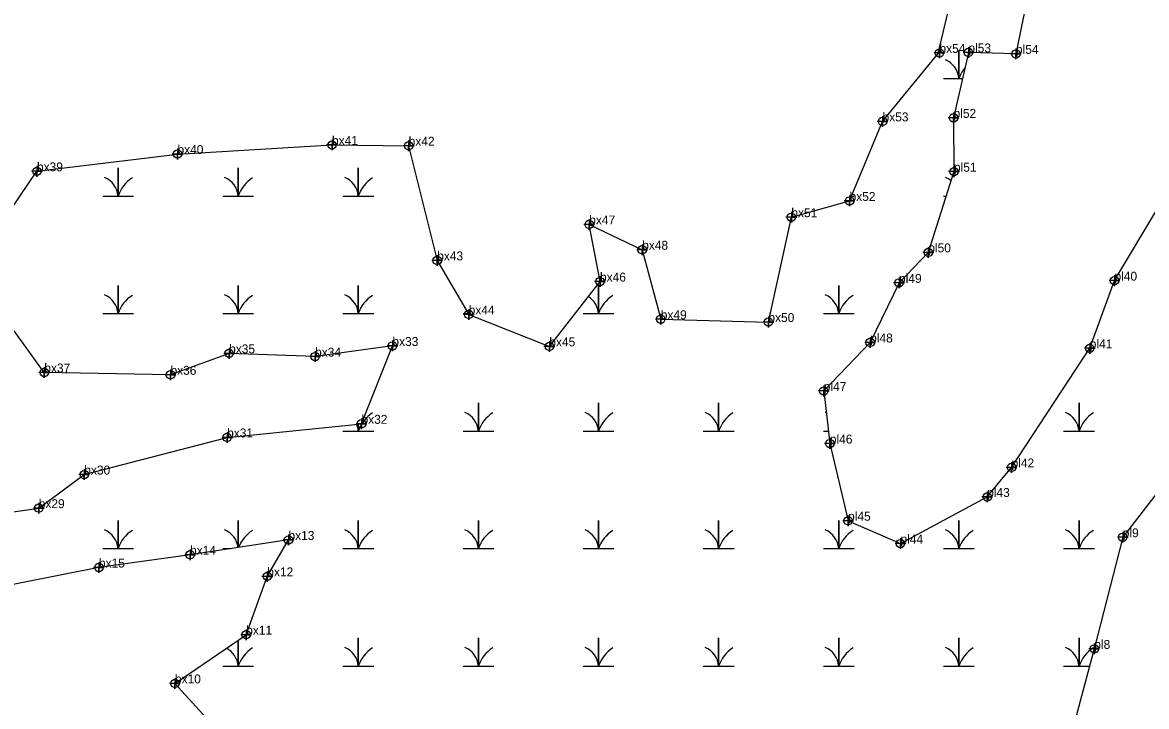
# Model space of a CAD drawing. Extents: x 2071991 to 2268989, y 436479 to 469629.
# Drawn here: x 2233643 to 2234271, y 438038 to 438420 of the extents above; entities that cross this region are included whole.
import ezdxf

# ---------------------------------------------------------------- set-up
doc = ezdxf.new("R2010")
doc.units = 0
for name, color, linetype in [('Exist Environmental Wetland Boundary', 7, 'Continuous'), ('Exist Environmental Wetland Boundary Cogo Comment', 7, 'Continuous'), ('Exist Environmental Wetland Boundary Cogo Point CELL', 7, 'Continuous'), ('Exist Hydro Swamp or Marsh', 7, 'Continuous')]:
    doc.layers.add(name, color=color, linetype=linetype)

msp = doc.modelspace()

# ---------------------------------------------------------------- linework, layer by layer
at = {"layer": 'Exist Environmental Wetland Boundary'}
for points in [[(2234206.5, 438606.87), (2234215.25, 438571.96), (2234220.38, 438527.18), (2234204.32, 438480.7), (2234205.77, 438439.37), (2234198.43, 438402.89), (2234171.84, 438403.69), (2234163.55, 438367.07), (2234163.75, 438336.95), (2234149.39, 438291.75), (2234133.01, 438274.68), (2234116.86, 438241.33), (2234090.91, 438214.16), (2234094.32, 438184.72), (2234104.51, 438141.53), (2234133.82, 438128.75), (2234182.34, 438154.84), (2234196, 438171.36), (2234239.71, 438238.05), (2234253.57, 438275.93), (2234280.54, 438321.15)], [(2233617.82, 438143.72), (2233651.73, 438148.58), (2233677.19, 438167.39), (2233757.1, 438188.17), (2233832.28, 438195.79), (2233849.59, 438239.38), (2233806.32, 438233.44), (2233758.21, 438235.23), (2233725.42, 438223.22), (2233654.83, 438224.52), (2233613.07, 438282.03), (2233650.73, 438337.13), (2233729.33, 438346.82), (2233815.78, 438351.89), (2233858.66, 438351.45), (2233874.62, 438287.27), (2233892.26, 438257), (2233937.37, 438239.13), (2233965.72, 438275.42), (2233959.69, 438307.4), (2233989.31, 438293.23), (2233999.72, 438254.31), (2234059.94, 438252.78), (2234072.76, 438311.45), (2234105.34, 438320.55), (2234123.8, 438365.08), (2234155, 438403.07), (2234167.55, 438456.6)], [(2234279.17, 438159.32), (2234258.17, 438132.28), (2234242.26, 438069.78), (2234230.04, 438024.51), (2234217.72, 437985.47), (2234249.98, 437934.73), (2234302.96, 437891.47)], [(2233878.1, 437800.94), (2233869.26, 437811.67), (2233815.49, 437844.98), (2233781.11, 437879.68), (2233780.48, 437926.57), (2233771.05, 437964.06), (2233759.41, 438015.96), (2233727.92, 438050.47), (2233767.76, 438077.73), (2233779.58, 438110.39), (2233791.43, 438130.77), (2233736.36, 438122.5), (2233685.39, 438115.35), (2233620.22, 438102.5)]]:
    msp.add_lwpolyline(points, dxfattribs=at)
at = {"layer": 'Exist Environmental Wetland Boundary Cogo Point CELL'}
for points in [[(2234155.64, 438406.39), (2234155.64, 438400.39), (2234155.64, 438403.39), (2234158.64, 438403.39), (2234152.64, 438403.39)], [(2234171.84, 438406.69), (2234171.84, 438400.69), (2234171.84, 438403.69), (2234174.84, 438403.69), (2234168.84, 438403.69)], [(2234198.43, 438405.89), (2234198.43, 438399.89), (2234198.43, 438402.89), (2234201.43, 438402.89), (2234195.43, 438402.89)], [(2234123.8, 438368.08), (2234123.8, 438362.08), (2234123.8, 438365.08), (2234126.8, 438365.08), (2234120.8, 438365.08)], [(2234163.55, 438370.07), (2234163.55, 438364.07), (2234163.55, 438367.07), (2234166.55, 438367.07), (2234160.55, 438367.07)], [(2233815.78, 438354.89), (2233815.78, 438348.89), (2233815.78, 438351.89), (2233818.78, 438351.89), (2233812.78, 438351.89)], [(2233858.66, 438354.45), (2233858.66, 438348.45), (2233858.66, 438351.45), (2233861.66, 438351.45), (2233855.66, 438351.45)], [(2233729.33, 438349.82), (2233729.33, 438343.82), (2233729.33, 438346.82), (2233732.33, 438346.82), (2233726.33, 438346.82)], [(2233650.73, 438340.13), (2233650.73, 438334.13), (2233650.73, 438337.13), (2233653.73, 438337.13), (2233647.73, 438337.13)], [(2234163.75, 438339.95), (2234163.75, 438333.95), (2234163.75, 438336.95), (2234166.75, 438336.95), (2234160.75, 438336.95)], [(2234105.34, 438323.55), (2234105.34, 438317.55), (2234105.34, 438320.55), (2234108.34, 438320.55), (2234102.34, 438320.55)], [(2234072.76, 438314.45), (2234072.76, 438308.45), (2234072.76, 438311.45), (2234075.76, 438311.45), (2234069.76, 438311.45)], [(2233959.69, 438310.4), (2233959.69, 438304.4), (2233959.69, 438307.4), (2233962.69, 438307.4), (2233956.69, 438307.4)], [(2233989.31, 438296.23), (2233989.31, 438290.23), (2233989.31, 438293.23), (2233992.31, 438293.23), (2233986.31, 438293.23)], [(2233874.62, 438290.27), (2233874.62, 438284.27), (2233874.62, 438287.27), (2233877.62, 438287.27), (2233871.62, 438287.27)], [(2234149.39, 438294.75), (2234149.39, 438288.75), (2234149.39, 438291.75), (2234152.39, 438291.75), (2234146.39, 438291.75)], [(2233965.72, 438278.42), (2233965.72, 438272.42), (2233965.72, 438275.42), (2233968.72, 438275.42), (2233962.72, 438275.42)], [(2234133.01, 438277.68), (2234133.01, 438271.68), (2234133.01, 438274.68), (2234136.01, 438274.68), (2234130.01, 438274.68)], [(2234253.57, 438278.93), (2234253.57, 438272.93), (2234253.57, 438275.93), (2234256.57, 438275.93), (2234250.57, 438275.93)], [(2233892.26, 438260), (2233892.26, 438254), (2233892.26, 438257), (2233895.26, 438257), (2233889.26, 438257)], [(2233999.72, 438257.31), (2233999.72, 438251.31), (2233999.72, 438254.31), (2234002.72, 438254.31), (2233996.72, 438254.31)], [(2234059.94, 438255.78), (2234059.94, 438249.78), (2234059.94, 438252.78), (2234062.94, 438252.78), (2234056.94, 438252.78)], [(2233849.59, 438242.38), (2233849.59, 438236.38), (2233849.59, 438239.38), (2233852.59, 438239.38), (2233846.59, 438239.38)], [(2233937.37, 438242.13), (2233937.37, 438236.13), (2233937.37, 438239.13), (2233940.37, 438239.13), (2233934.37, 438239.13)], [(2234116.86, 438244.33), (2234116.86, 438238.33), (2234116.86, 438241.33), (2234119.86, 438241.33), (2234113.86, 438241.33)], [(2234239.71, 438241.05), (2234239.71, 438235.05), (2234239.71, 438238.05), (2234242.71, 438238.05), (2234236.71, 438238.05)], [(2233758.21, 438238.23), (2233758.21, 438232.23), (2233758.21, 438235.23), (2233761.21, 438235.23), (2233755.21, 438235.23)], [(2233806.32, 438236.44), (2233806.32, 438230.44), (2233806.32, 438233.44), (2233809.32, 438233.44), (2233803.32, 438233.44)], [(2233654.83, 438227.52), (2233654.83, 438221.52), (2233654.83, 438224.52), (2233657.83, 438224.52), (2233651.83, 438224.52)], [(2233725.42, 438226.22), (2233725.42, 438220.22), (2233725.42, 438223.22), (2233728.42, 438223.22), (2233722.42, 438223.22)], [(2234090.91, 438217.16), (2234090.91, 438211.16), (2234090.91, 438214.16), (2234093.91, 438214.16), (2234087.91, 438214.16)], [(2233832.28, 438198.79), (2233832.28, 438192.79), (2233832.28, 438195.79), (2233835.28, 438195.79), (2233829.28, 438195.79)], [(2233757.1, 438191.17), (2233757.1, 438185.17), (2233757.1, 438188.17), (2233760.1, 438188.17), (2233754.1, 438188.17)], [(2234094.32, 438187.72), (2234094.32, 438181.72), (2234094.32, 438184.72), (2234097.32, 438184.72), (2234091.32, 438184.72)], [(2233677.19, 438170.39), (2233677.19, 438164.39), (2233677.19, 438167.39), (2233680.19, 438167.39), (2233674.19, 438167.39)], [(2234196, 438174.36), (2234196, 438168.36), (2234196, 438171.36), (2234199, 438171.36), (2234193, 438171.36)], [(2234182.34, 438157.84), (2234182.34, 438151.84), (2234182.34, 438154.84), (2234185.34, 438154.84), (2234179.34, 438154.84)], [(2233651.73, 438151.58), (2233651.73, 438145.58), (2233651.73, 438148.58), (2233654.73, 438148.58), (2233648.73, 438148.58)], [(2234104.51, 438144.53), (2234104.51, 438138.53), (2234104.51, 438141.53), (2234107.51, 438141.53), (2234101.51, 438141.53)], [(2233791.43, 438133.77), (2233791.43, 438127.77), (2233791.43, 438130.77), (2233794.43, 438130.77), (2233788.43, 438130.77)], [(2234258.17, 438135.28), (2234258.17, 438129.28), (2234258.17, 438132.28), (2234261.17, 438132.28), (2234255.17, 438132.28)], [(2234133.82, 438131.75), (2234133.82, 438125.75), (2234133.82, 438128.75), (2234136.82, 438128.75), (2234130.82, 438128.75)], [(2233736.36, 438125.5), (2233736.36, 438119.5), (2233736.36, 438122.5), (2233739.36, 438122.5), (2233733.36, 438122.5)], [(2233685.39, 438118.35), (2233685.39, 438112.35), (2233685.39, 438115.35), (2233688.39, 438115.35), (2233682.39, 438115.35)], [(2233779.58, 438113.39), (2233779.58, 438107.39), (2233779.58, 438110.39), (2233782.58, 438110.39), (2233776.58, 438110.39)], [(2233767.76, 438080.73), (2233767.76, 438074.73), (2233767.76, 438077.73), (2233770.76, 438077.73), (2233764.76, 438077.73)], [(2234242.26, 438072.78), (2234242.26, 438066.78), (2234242.26, 438069.78), (2234245.26, 438069.78), (2234239.26, 438069.78)], [(2233727.92, 438053.47), (2233727.92, 438047.47), (2233727.92, 438050.47), (2233730.92, 438050.47), (2233724.92, 438050.47)]]:
    msp.add_lwpolyline(points, dxfattribs=at)
for centre in [(2234155.64, 438403.39), (2234171.84, 438403.69), (2234198.43, 438402.89), (2234123.8, 438365.08), (2234163.55, 438367.07), (2233815.78, 438351.89), (2233858.66, 438351.45), (2233729.33, 438346.82), (2233650.73, 438337.13), (2234163.75, 438336.95), (2234105.34, 438320.55), (2233959.69, 438307.4), (2234072.76, 438311.45), (2233989.31, 438293.23), (2233874.62, 438287.27), (2234149.39, 438291.75), (2233965.72, 438275.42), (2234133.01, 438274.68), (2234253.57, 438275.93), (2233892.26, 438257), (2233999.72, 438254.31), (2234059.94, 438252.78), (2233849.59, 438239.38), (2233937.37, 438239.13), (2234116.86, 438241.33), (2234239.71, 438238.05), (2233758.21, 438235.23), (2233806.32, 438233.44), (2233654.83, 438224.52), (2233725.42, 438223.22), (2234090.91, 438214.16), (2233832.28, 438195.79), (2233757.1, 438188.17), (2234094.32, 438184.72), (2233677.19, 438167.39), (2234196, 438171.36), (2234182.34, 438154.84), (2233651.73, 438148.58), (2234104.51, 438141.53), (2233791.43, 438130.77), (2234258.17, 438132.28), (2234133.82, 438128.75), (2233736.36, 438122.5), (2233685.39, 438115.35), (2233779.58, 438110.39), (2233767.76, 438077.73), (2234242.26, 438069.78), (2233727.92, 438050.47)]:
    msp.add_circle(centre, 2.34, dxfattribs=at)
at = {"layer": 'Exist Hydro Swamp or Marsh'}
for p, q in [((2234106.46, 438323.25), (2234107.9, 438323.25)), ((2234157.9, 438323.25), (2234159.4, 438323.25)), ((2233889.09, 438257.47), (2233891.98, 438257.47)), ((2234090.7, 438191.69), (2234093.51, 438191.69)), ((2233754.68, 438125.91), (2233759.08, 438125.91))]:
    msp.add_line(p, q, dxfattribs=at)
for points in [[(2234157.9, 438389.04), (2234166.5, 438389.04), (2234166.5, 438404.82), (2234166.5, 438389.04), (2234168.53, 438389.04)], [(2233687.48, 438323.25), (2233696.08, 438323.25), (2233696.08, 438339.04), (2233696.08, 438323.25), (2233704.68, 438323.25)], [(2233754.68, 438323.25), (2233763.28, 438323.25), (2233763.28, 438339.04), (2233763.28, 438323.25), (2233771.89, 438323.25)], [(2233821.89, 438323.25), (2233830.49, 438323.25), (2233830.49, 438339.04), (2233830.49, 438323.25), (2233839.09, 438323.25)], [(2233687.48, 438257.47), (2233696.08, 438257.47), (2233696.08, 438273.25), (2233696.08, 438257.47), (2233704.68, 438257.47)], [(2233754.68, 438257.47), (2233763.28, 438257.47), (2233763.28, 438273.25), (2233763.28, 438257.47), (2233771.89, 438257.47)], [(2233821.89, 438257.47), (2233830.49, 438257.47), (2233830.49, 438273.25), (2233830.49, 438257.47), (2233839.09, 438257.47)], [(2233956.29, 438257.47), (2233964.89, 438257.47), (2233964.89, 438273.25), (2233964.89, 438257.47), (2233973.5, 438257.47)], [(2234090.7, 438257.47), (2234099.3, 438257.47), (2234099.3, 438273.25), (2234099.3, 438257.47), (2234107.9, 438257.47)], [(2233889.09, 438191.69), (2233897.69, 438191.69), (2233897.69, 438207.47), (2233897.69, 438191.69), (2233906.29, 438191.69)], [(2233956.29, 438191.69), (2233964.89, 438191.69), (2233964.89, 438207.47), (2233964.89, 438191.69), (2233973.5, 438191.69)], [(2234023.5, 438191.69), (2234032.1, 438191.69), (2234032.1, 438207.47), (2234032.1, 438191.69), (2234040.7, 438191.69)], [(2234225.11, 438191.69), (2234233.71, 438191.69), (2234233.71, 438207.47), (2234233.71, 438191.69), (2234242.31, 438191.69)], [(2233821.89, 438191.69), (2233830.49, 438191.69), (2233830.49, 438195.61)], [(2233830.49, 438195.61), (2233830.49, 438191.69), (2233839.09, 438191.69)], [(2233687.48, 438125.91), (2233696.08, 438125.91), (2233696.08, 438141.69), (2233696.08, 438125.91), (2233704.68, 438125.91)], [(2233763.28, 438126.54), (2233763.28, 438141.69), (2233763.28, 438126.54)], [(2233821.89, 438125.91), (2233830.49, 438125.91), (2233830.49, 438141.69), (2233830.49, 438125.91), (2233839.09, 438125.91)], [(2233889.09, 438125.91), (2233897.69, 438125.91), (2233897.69, 438141.69), (2233897.69, 438125.91), (2233906.29, 438125.91)], [(2233956.29, 438125.91), (2233964.89, 438125.91), (2233964.89, 438141.69), (2233964.89, 438125.91), (2233973.5, 438125.91)], [(2234023.5, 438125.91), (2234032.1, 438125.91), (2234032.1, 438141.69), (2234032.1, 438125.91), (2234040.7, 438125.91)], [(2234090.7, 438125.91), (2234099.3, 438125.91), (2234099.3, 438141.69), (2234099.3, 438125.91), (2234107.9, 438125.91)], [(2234157.9, 438125.91), (2234166.5, 438125.91), (2234166.5, 438141.69), (2234166.5, 438125.91), (2234175.11, 438125.91)], [(2234225.11, 438125.91), (2234233.71, 438125.91), (2234233.71, 438141.69), (2234233.71, 438125.91), (2234242.31, 438125.91)], [(2233821.89, 438060.13), (2233830.49, 438060.13), (2233830.49, 438075.91), (2233830.49, 438060.13), (2233839.09, 438060.13)], [(2233889.09, 438060.13), (2233897.69, 438060.13), (2233897.69, 438075.91), (2233897.69, 438060.13), (2233906.29, 438060.13)], [(2233956.29, 438060.13), (2233964.89, 438060.13), (2233964.89, 438075.91), (2233964.89, 438060.13), (2233973.5, 438060.13)], [(2234023.5, 438060.13), (2234032.1, 438060.13), (2234032.1, 438075.91), (2234032.1, 438060.13), (2234040.7, 438060.13)], [(2234090.7, 438060.13), (2234099.3, 438060.13), (2234099.3, 438075.91), (2234099.3, 438060.13), (2234107.9, 438060.13)], [(2234157.9, 438060.13), (2234166.5, 438060.13), (2234166.5, 438075.91), (2234166.5, 438060.13), (2234175.11, 438060.13)], [(2234225.11, 438060.13), (2234233.71, 438060.13), (2234233.71, 438075.91), (2234233.71, 438060.13), (2234239.66, 438060.13)], [(2233754.68, 438060.13), (2233763.28, 438060.13), (2233763.28, 438074.67)], [(2233763.28, 438074.67), (2233763.28, 438060.13), (2233771.89, 438060.13)]]:
    msp.add_lwpolyline(points, dxfattribs=at)
for centre, radius, start, end in [((2234154.24, 438388.15), 12.3, 4.14034, 67.53497), ((2234184.75, 438382.97), 19.22, 140.44776, 161.62219), ((2233683.82, 438322.37), 12.3, 4.14034, 67.53497), ((2233714.32, 438317.19), 19.22, 122.12745, 161.62219), ((2233751.02, 438322.37), 12.3, 4.14034, 67.53497), ((2233781.53, 438317.19), 19.22, 122.12745, 161.62219), ((2233818.22, 438322.37), 12.3, 4.14034, 67.53497), ((2233848.73, 438317.19), 19.22, 122.12745, 161.62219), ((2234154.24, 438322.37), 12.3, 50.15165, 67.53497), ((2233683.82, 438256.59), 12.3, 4.14034, 67.53497), ((2233714.32, 438251.41), 19.22, 122.12745, 161.62219), ((2233751.02, 438256.59), 12.3, 4.14034, 67.53497), ((2233781.53, 438251.41), 19.22, 122.12745, 161.62219), ((2233818.22, 438256.59), 12.3, 4.14034, 67.53497), ((2233848.73, 438251.41), 19.22, 122.12745, 161.62219), ((2233952.63, 438256.59), 12.3, 4.14034, 57.97661), ((2233983.14, 438251.41), 19.22, 122.12745, 161.62219), ((2234087.03, 438256.59), 12.3, 4.14034, 67.53497), ((2234117.54, 438251.41), 19.22, 122.12745, 161.62219), ((2233848.73, 438185.63), 19.22, 122.12745, 161.62219), ((2233885.43, 438190.81), 12.3, 4.14034, 67.53497), ((2233915.93, 438185.63), 19.22, 122.12745, 161.62219), ((2233952.63, 438190.81), 12.3, 4.14034, 67.53497), ((2233983.14, 438185.63), 19.22, 122.12745, 161.62219), ((2234019.83, 438190.81), 12.3, 4.14034, 67.53497), ((2234050.34, 438185.63), 19.22, 122.12745, 161.62219), ((2234087.03, 438190.81), 12.3, 64.51047, 67.53497), ((2234221.44, 438190.81), 12.3, 4.14034, 67.53497), ((2234251.95, 438185.63), 19.22, 122.12745, 161.62219), ((2233818.22, 438190.81), 12.3, 4.14034, 22.51982), ((2233683.82, 438125.03), 12.3, 4.14034, 67.53497), ((2233714.32, 438119.85), 19.22, 122.12745, 161.62219), ((2233751.02, 438125.03), 12.3, 7.05119, 67.53497), ((2233781.53, 438119.85), 19.22, 122.12745, 159.51655), ((2233818.22, 438125.03), 12.3, 4.14034, 67.53497), ((2233848.73, 438119.85), 19.22, 122.12745, 161.62219), ((2233885.43, 438125.03), 12.3, 4.14034, 67.53497), ((2233915.93, 438119.85), 19.22, 122.12745, 161.62219), ((2233952.63, 438125.03), 12.3, 4.14034, 67.53497), ((2233983.14, 438119.85), 19.22, 122.12745, 161.62219), ((2234019.83, 438125.03), 12.3, 4.14034, 67.53497), ((2234050.34, 438119.85), 19.22, 122.12745, 161.62219), ((2234087.03, 438125.03), 12.3, 4.14034, 67.53497), ((2234117.54, 438119.85), 19.22, 122.12745, 161.62219), ((2234154.24, 438125.03), 12.3, 4.14034, 67.53497), ((2234184.75, 438119.85), 19.22, 122.12745, 161.62219), ((2234221.44, 438125.03), 12.3, 4.14034, 67.53497), ((2234251.95, 438119.85), 19.22, 122.12745, 161.62219), ((2233751.02, 438059.24), 12.3, 4.14034, 62.54833), ((2233781.53, 438054.07), 19.22, 122.12745, 161.62219), ((2233818.22, 438059.24), 12.3, 4.14034, 67.53497), ((2233848.73, 438054.07), 19.22, 122.12745, 161.62219), ((2233885.43, 438059.24), 12.3, 4.14034, 67.53497), ((2233915.93, 438054.07), 19.22, 122.12745, 161.62219), ((2233952.63, 438059.24), 12.3, 4.14034, 67.53497), ((2233983.14, 438054.07), 19.22, 122.12745, 161.62219), ((2234019.83, 438059.24), 12.3, 4.14034, 67.53497), ((2234050.34, 438054.07), 19.22, 122.12745, 161.62219), ((2234087.03, 438059.24), 12.3, 4.14034, 67.53497), ((2234117.54, 438054.07), 19.22, 122.12745, 161.62219), ((2234154.24, 438059.24), 12.3, 4.14034, 67.53497), ((2234184.75, 438054.07), 19.22, 122.12745, 161.62219), ((2234221.44, 438059.24), 12.3, 4.14034, 67.53497), ((2234251.95, 438054.07), 19.22, 122.12745, 161.62219)]:
    msp.add_arc(centre, radius, start, end, dxfattribs=at)

# ---------------------------------------------------------------- texts
at = {"layer": 'Exist Environmental Wetland Boundary Cogo Comment'}
for s, p in [('bx54', (2234155.64, 438403.39)), ('pl53', (2234171.84, 438403.69)), ('pl54', (2234198.43, 438402.89)), ('pl52', (2234163.55, 438367.07)), ('bx53', (2234123.8, 438365.08)), ('bx40', (2233729.33, 438346.82)), ('bx41', (2233815.78, 438351.89)), ('bx42', (2233858.66, 438351.45)), ('bx39', (2233650.73, 438337.13)), ('pl51', (2234163.75, 438336.95)), ('bx52', (2234105.34, 438320.55)), ('bx51', (2234072.76, 438311.45)), ('bx47', (2233959.69, 438307.4)), ('bx48', (2233989.31, 438293.23)), ('pl50', (2234149.39, 438291.75)), ('bx43', (2233874.62, 438287.27)), ('bx46', (2233965.72, 438275.42)), ('pl49', (2234133.01, 438274.68)), ('pl40', (2234253.57, 438275.93)), ('bx44', (2233892.26, 438257)), ('bx49', (2233999.72, 438254.31)), ('bx50', (2234059.94, 438252.78)), ('pl48', (2234116.86, 438241.33)), ('bx35', (2233758.21, 438235.23)), ('bx33', (2233849.59, 438239.38)), ('bx45', (2233937.37, 438239.13)), ('pl41', (2234239.71, 438238.05)), ('bx34', (2233806.32, 438233.44)), ('bx37', (2233654.83, 438224.52)), ('bx36', (2233725.42, 438223.22)), ('pl47', (2234090.91, 438214.16)), ('bx32', (2233832.28, 438195.79)), ('bx31', (2233757.1, 438188.17)), ('pl46', (2234094.32, 438184.72)), ('pl42', (2234196, 438171.36)), ('bx30', (2233677.19, 438167.39)), ('pl43', (2234182.34, 438154.84)), ('bx29', (2233651.73, 438148.58)), ('pl45', (2234104.51, 438141.53)), ('bx13', (2233791.43, 438130.77)), ('pl44', (2234133.82, 438128.75)), ('pl9', (2234258.17, 438132.28)), ('bx14', (2233736.36, 438122.5)), ('bx15', (2233685.39, 438115.35)), ('bx12', (2233779.58, 438110.39)), ('bx11', (2233767.76, 438077.73)), ('pl8', (2234242.26, 438069.78)), ('bx10', (2233727.92, 438050.47))]:
    msp.add_text(s, height=5, dxfattribs=at).set_placement(p)

doc.saveas('drawing.dxf')
